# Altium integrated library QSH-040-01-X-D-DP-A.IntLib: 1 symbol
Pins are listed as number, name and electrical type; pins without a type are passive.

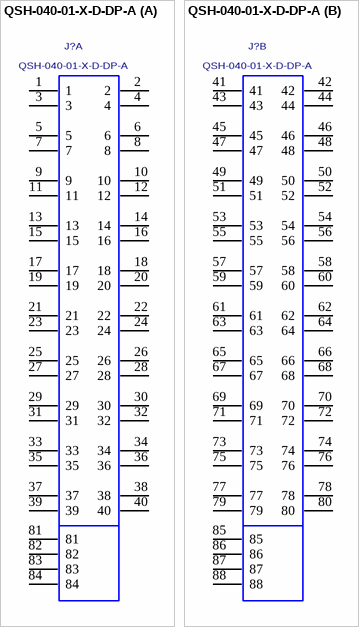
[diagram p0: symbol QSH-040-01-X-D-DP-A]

## QSH-040-01-X-D-DP-A
designator J?
HIGH SPEED SOCKET, 0.5mm PITCH, DIFFERENTIAL PAIRS, 80 PINS; MANUFACTURER: SAMTEC
footprint QSH-040-01-X-D-DP-A
part A pins: 1, 2, 3, 4, 5, 6, 7, 8, 9, 10, 11, 12, 13, 14, 15, 16, 17, 18, 19, 20, 21, 22, 23, 24, 25, 26, 27, 28, 29, 30, 31, 32, 33, 34, 35, 36, 37, 38, 39, 40, 81, 82, 83, 84
part B pins: 41, 42, 43, 44, 45, 46, 47, 48, 49, 50, 51, 52, 53, 54, 55, 56, 57, 58, 59, 60, 61, 62, 63, 64, 65, 66, 67, 68, 69, 70, 71, 72, 73, 74, 75, 76, 77, 78, 79, 80, 85, 86, 87, 88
